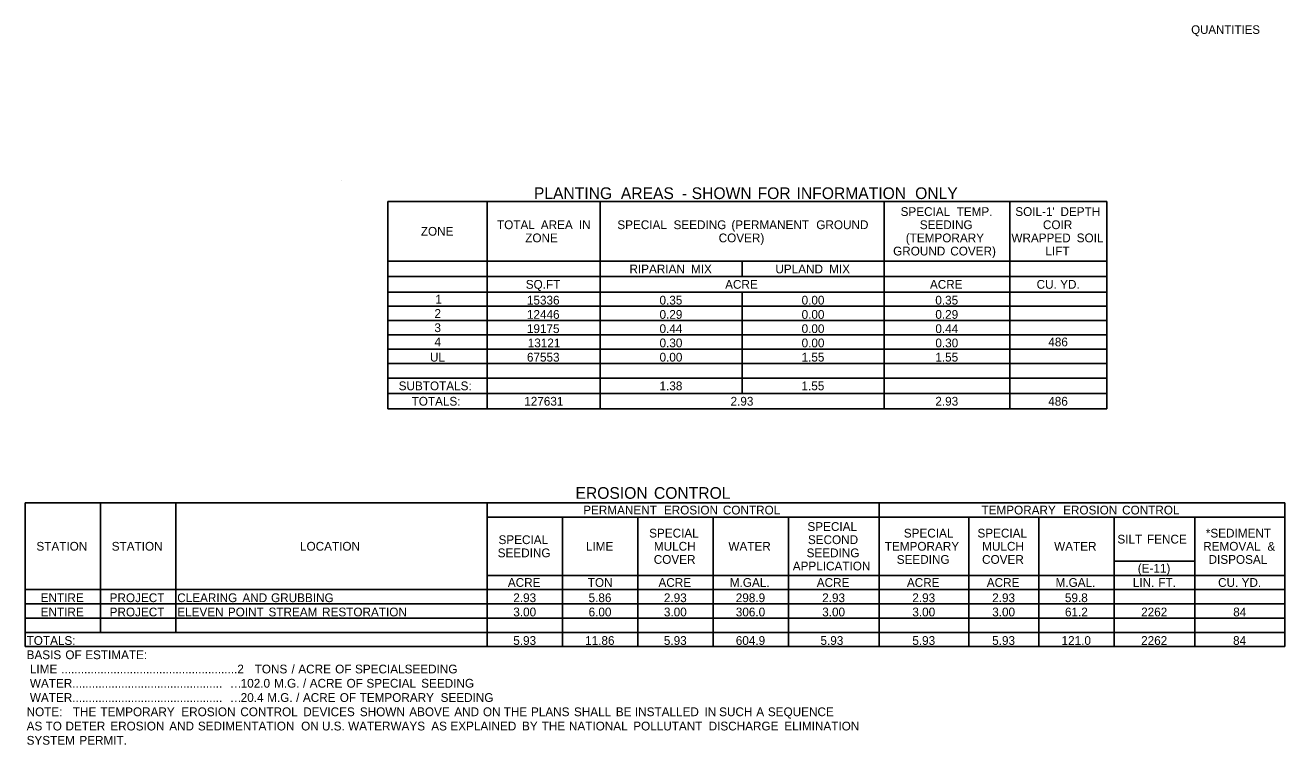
# Model space of a CAD drawing. Extents: x -2001791 to 62654501, y -2521700 to -592476.
# Drawn here: x -2001253 to -2000392, y -592968 to -592476 of the extents above; entities that cross this region are included whole.
import ezdxf

# ---------------------------------------------------------------- set-up
doc = ezdxf.new("R2010")
doc.units = 0
for name, color, linetype in [('Default', 7, 'Continuous'), ('R_Border', 7, 'Continuous'), ('R_Border Prem', 7, 'Continuous')]:
    doc.layers.add(name, color=color, linetype=linetype)

msp = doc.modelspace()

# ---------------------------------------------------------------- linework, layer by layer
at = {"layer": 'Default'}
for p, q in [((-2001005.43, -592596.06), (-2000514.03, -592596.06)), ((-2001005.43, -592738.02), (-2001005.43, -592596.06)), ((-2001005.43, -592738.02), (-2001005.43, -592596.06)), ((-2000937.57, -592738.02), (-2000937.57, -592596.06)), ((-2000860.35, -592738.02), (-2000860.35, -592596.06)), ((-2000666.13, -592738.02), (-2000666.13, -592596.06)), ((-2000580.33, -592738.02), (-2000580.33, -592596.06)), ((-2000514.03, -592738.02), (-2000514.03, -592596.06)), ((-2001005.43, -592637.01), (-2000514.03, -592637.01)), ((-2000763.24, -592647.54), (-2000763.24, -592637.01)), ((-2001005.43, -592647.54), (-2000514.03, -592647.54)), ((-2000580.33, -592647.54), (-2000514.03, -592647.54)), ((-2001005.43, -592658.07), (-2000514.03, -592658.07)), ((-2000763.24, -592727.49), (-2000763.24, -592658.07)), ((-2001005.43, -592667.82), (-2000514.03, -592667.82)), ((-2001005.43, -592677.57), (-2000514.03, -592677.57)), ((-2001005.43, -592687.32), (-2000514.03, -592687.32)), ((-2001005.43, -592697.07), (-2000514.03, -592697.07)), ((-2001005.43, -592706.82), (-2000514.03, -592706.82)), ((-2000580.33, -592706.82), (-2000514.03, -592706.82)), ((-2001005.43, -592716.96), (-2000937.57, -592716.96)), ((-2001005.43, -592716.96), (-2000937.57, -592716.96)), ((-2000937.57, -592716.96), (-2000514.03, -592716.96)), ((-2000937.57, -592716.96), (-2000514.03, -592716.96)), ((-2001005.43, -592727.49), (-2000514.03, -592727.49)), ((-2000937.57, -592738.02), (-2000937.57, -592727.49)), ((-2000580.33, -592727.49), (-2000514.03, -592727.49)), ((-2001005.43, -592738.02), (-2000514.03, -592738.02)), ((-2001253.42, -592802.3), (-2000392.3, -592802.3)), ((-2001253.42, -592900.58), (-2001253.42, -592802.3)), ((-2001253.42, -592900.58), (-2001253.42, -592802.3)), ((-2001201.94, -592890.83), (-2001201.94, -592802.3)), ((-2001150.46, -592890.83), (-2001150.46, -592802.3)), ((-2000937.52, -592900.58), (-2000937.52, -592802.3)), ((-2000669.59, -592812.05), (-2000669.59, -592802.3)), ((-2000669.59, -592900.58), (-2000669.59, -592802.3)), ((-2000392.3, -592900.58), (-2000392.3, -592802.3)), ((-2000937.52, -592812.05), (-2000392.3, -592812.05)), ((-2000886.04, -592900.58), (-2000886.04, -592812.05)), ((-2000834.56, -592900.58), (-2000834.56, -592812.05)), ((-2000783.08, -592900.58), (-2000783.08, -592812.05)), ((-2000731.6, -592900.58), (-2000731.6, -592812.05)), ((-2000608.36, -592900.58), (-2000608.36, -592812.05)), ((-2000560.39, -592900.58), (-2000560.39, -592812.05)), ((-2000508.91, -592900.58), (-2000508.91, -592812.05)), ((-2000453.92, -592900.58), (-2000453.92, -592812.05)), ((-2000508.91, -592842.08), (-2000453.92, -592842.08)), ((-2000937.52, -592851.83), (-2000392.3, -592851.83)), ((-2000886.04, -592881.08), (-2000886.04, -592851.83)), ((-2000834.56, -592881.08), (-2000834.56, -592851.83)), ((-2000783.08, -592881.08), (-2000783.08, -592851.83)), ((-2000731.6, -592881.08), (-2000731.6, -592851.83)), ((-2000669.59, -592881.08), (-2000669.59, -592851.83)), ((-2000608.36, -592881.08), (-2000608.36, -592851.83)), ((-2000560.39, -592881.08), (-2000560.39, -592851.83)), ((-2000508.91, -592881.08), (-2000508.91, -592851.83)), ((-2000453.92, -592851.83), (-2000392.3, -592851.83)), ((-2000453.92, -592881.08), (-2000453.92, -592851.83)), ((-2001253.42, -592861.58), (-2000392.3, -592861.58)), ((-2001201.94, -592881.08), (-2001201.94, -592861.58)), ((-2001150.46, -592881.08), (-2001150.46, -592861.58)), ((-2000937.52, -592881.08), (-2000937.52, -592861.58)), ((-2001253.42, -592871.33), (-2000392.3, -592871.33)), ((-2001253.42, -592881.08), (-2000392.3, -592881.08)), ((-2001253.42, -592890.83), (-2000392.3, -592890.83)), ((-2000937.52, -592900.58), (-2000937.52, -592890.83)), ((-2000886.04, -592900.58), (-2000886.04, -592890.83)), ((-2000608.36, -592900.58), (-2000608.36, -592890.83)), ((-2000560.39, -592900.58), (-2000560.39, -592890.83)), ((-2000453.92, -592900.58), (-2000453.92, -592890.83)), ((-2001253.42, -592900.58), (-2000392.3, -592900.58))]:
    msp.add_line(p, q, dxfattribs=at)
at = {"layer": 'R_Border'}
msp.add_line((-2001037.41, -592582.02), (-2001037.41, -592582.02), dxfattribs=at)

# ---------------------------------------------------------------- texts
at = {"layer": 'Default'}
for s, height, p in [('PLANTING', 8, (-2000905.65, -592594.46)), (' AREAS', 8, (-2000849.19, -592594.46)), (' SHOWN', 8, (-2000800.76, -592594.46)), (' FOR', 8, (-2000755.7, -592594.46)), (' INFORMATION', 8, (-2000729.06, -592594.46)), (' ONLY', 8, (-2000647.99, -592594.46)), (' -', 8, (-2000807.5, -592594.46)), ('SPECIAL', 6, (-2000654.96, -592606.04)), (' TEMP.', 6, (-2000618.87, -592606.04)), ("SOIL-1'", 6, (-2000576.55, -592606.04)), (' DEPTH', 6, (-2000547.91, -592606.04)), ('ZONE', 6, (-2000982.94, -592619.54)), ('TOTAL', 6, (-2000930.85, -592615.04)), (' AREA', 6, (-2000903.16, -592615.04)), (' IN', 6, (-2000877.11, -592615.04)), (' SPECIAL', 6, (-2000850.84, -592615.04)), (' SEEDING', 6, (-2000812.42, -592615.04)), (' (PERMANENT', 6, (-2000772.86, -592615.04)), (' GROUND', 6, (-2000714.82, -592615.04)), ('SEEDING', 6, (-2000641.85, -592615.04)), ('COIR', 6, (-2000557.64, -592615.04)), ('ZONE', 6, (-2000911.56, -592624.04)), ('COVER)', 6, (-2000779.33, -592624.04)), ('(TEMPORARY', 6, (-2000651.42, -592624.04)), ('WRAPPED', 6, (-2000579.22, -592624.04)), (' SOIL', 6, (-2000536.78, -592624.04)), ('GROUND', 6, (-2000660.07, -592633.04)), (' COVER)', 6, (-2000623.22, -592633.04)), ('LIFT', 6, (-2000555.94, -592633.04)), ('RIPARIAN', 6, (-2000840.33, -592645.28)), (' MIX', 6, (-2000800.48, -592645.28)), ('UPLAND', 6, (-2000740.56, -592645.28)), (' MIX', 6, (-2000706.04, -592645.28)), ('SQ.FT', 6, (-2000911.22, -592655.81)), ('ACRE', 6, (-2000774.91, -592655.81)), ('ACRE', 6, (-2000634.9, -592655.81)), ('CU.', 6, (-2000561.97, -592655.81)), (' YD.', 6, (-2000548.11, -592655.81)), ('1', 6, (-2000973.06, -592665.95)), ('15336', 6, (-2000910.42, -592666.62)), ('0.35', 6, (-2000819.78, -592666.62)), ('0.00', 6, (-2000722.64, -592666.62)), ('0.35', 6, (-2000631.22, -592666.62)), ('2', 6, (-2000973.61, -592675.7)), ('12446', 6, (-2000910.42, -592676.37)), ('0.29', 6, (-2000819.76, -592676.37)), ('0.00', 6, (-2000722.64, -592676.37)), ('0.29', 6, (-2000631.2, -592676.37)), ('3', 6, (-2000973.64, -592685.45)), ('19175', 6, (-2000910.44, -592686.12)), ('0.44', 6, (-2000819.75, -592686.12)), ('0.00', 6, (-2000722.64, -592686.12)), ('0.44', 6, (-2000631.18, -592686.12)), ('4', 6, (-2000973.63, -592695.2)), ('13121', 6, (-2000909.84, -592695.87)), ('0.30', 6, (-2000819.75, -592695.87)), ('0.00', 6, (-2000722.64, -592695.87)), ('0.30', 6, (-2000631.18, -592695.87)), ('486', 6, (-2000553.98, -592695.2)), ('UL', 6, (-2000976.71, -592705.62)), ('67553', 6, (-2000910.42, -592705.62)), ('0.00', 6, (-2000819.75, -592705.62)), ('1.55', 6, (-2000722.67, -592705.62)), ('1.55', 6, (-2000631.22, -592705.62)), ('SUBTOTALS:', 6, (-2000998.1, -592725.23)), ('1.38', 6, (-2000819.76, -592725.23)), ('1.55', 6, (-2000722.71, -592725.23)), ('TOTALS:', 6, (-2000989.25, -592735.76)), ('127631', 6, (-2000912.26, -592735.76)), ('2.93', 6, (-2000771.21, -592735.76)), ('2.93', 6, (-2000631.2, -592735.76)), ('486', 6, (-2000554.02, -592735.76)), ('EROSION', 8, (-2000877.21, -592799.47)), (' CONTROL', 8, (-2000826.55, -592799.47)), ('PERMANENT', 6, (-2000871.94, -592810.17)), (' EROSION', 6, (-2000819.01, -592810.17)), (' CONTROL', 6, (-2000778.69, -592810.17)), ('TEMPORARY', 6, (-2000599.66, -592810.17)), (' EROSION', 6, (-2000546.08, -592810.17)), (' CONTROL', 6, (-2000505.76, -592810.17)), ('SPECIAL', 6, (-2000826.86, -592825.94)), ('SPECIAL', 6, (-2000718.64, -592821.44)), ('    SPECIAL', 6, (-2000661.67, -592825.94)), ('SPECIAL', 6, (-2000602.42, -592825.94)), ('*SEDIMENT', 6, (-2000446.31, -592825.94)), ('STATION', 6, (-2001245.74, -592834.94)), ('STATION', 6, (-2001194.26, -592834.94)), ('LOCATION', 6, (-2001065.54, -592834.94)), ('SPECIAL', 6, (-2000929.82, -592830.44)), ('LIME', 6, (-2000870.1, -592834.94)), ('MULCH', 6, (-2000823.63, -592834.94)), ('WATER', 6, (-2000772.69, -592834.94)), ('SECOND', 6, (-2000718.32, -592830.44)), ('TEMPORARY', 6, (-2000665.77, -592834.94)), ('MULCH', 6, (-2000599.19, -592834.94)), ('WATER', 6, (-2000550, -592834.94)), ('SILT', 6, (-2000506.74, -592830.06)), (' FENCE', 6, (-2000488.75, -592830.06)), ('REMOVAL', 6, (-2000448.07, -592834.94)), (' &', 6, (-2000406.4, -592834.94)), ('SEEDING', 6, (-2000930.39, -592839.44)), ('COVER', 6, (-2000823.71, -592843.94)), ('SEEDING', 6, (-2000719.21, -592839.44)), ('SEEDING', 6, (-2000657.59, -592843.94)), ('COVER', 6, (-2000599.26, -592843.94)), ('DISPOSAL', 6, (-2000444.41, -592843.94)), ('APPLICATION', 6, (-2000728.67, -592848.44)), ('(E-11)', 6, (-2000492.84, -592849.95)), ('ACRE', 6, (-2000923.45, -592859.7)), ('TON', 6, (-2000868.81, -592859.7)), ('ACRE', 6, (-2000820.49, -592859.7)), ('M.GAL.', 6, (-2000771.72, -592859.7)), ('ACRE', 6, (-2000712.26, -592859.7)), ('ACRE', 6, (-2000650.64, -592859.7)), ('ACRE', 6, (-2000596.04, -592859.7)), ('M.GAL.', 6, (-2000549.03, -592859.7)), ('LIN.', 6, (-2000496.2, -592859.7)), (' FT.', 6, (-2000480.95, -592859.7)), ('CU.', 6, (-2000437.9, -592859.7)), (' YD.', 6, (-2000424.04, -592859.7)), ('ENTIRE', 6, (-2001242.83, -592870.13)), ('PROJECT', 6, (-2001195.68, -592870.13)), ('CLEARING', 6, (-2001149.48, -592870.13)), (' AND', 6, (-2001107.15, -592870.13)), (' GRUBBING', 6, (-2001087.57, -592870.13)), ('2.93', 6, (-2000919.74, -592870.13)), ('5.86', 6, (-2000868.26, -592870.13)), ('2.93', 6, (-2000816.78, -592870.13)), ('298.9', 6, (-2000767.64, -592870.13)), ('2.93', 6, (-2000708.56, -592870.13)), ('2.93', 6, (-2000646.94, -592870.13)), ('2.93', 6, (-2000592.34, -592870.13)), ('59.8', 6, (-2000542.62, -592870.13)), ('ENTIRE', 6, (-2001242.83, -592879.88)), ('PROJECT', 6, (-2001195.68, -592879.88)), ('ELEVEN', 6, (-2001149.48, -592879.88)), (' POINT', 6, (-2001117.08, -592879.88)), (' STREAM', 6, (-2001089.31, -592879.88)), (' RESTORATION', 6, (-2001052.67, -592879.88)), ('3.00', 6, (-2000919.73, -592879.88)), ('6.00', 6, (-2000868.25, -592879.88)), ('3.00', 6, (-2000816.77, -592879.88)), ('306.0', 6, (-2000767.62, -592879.88)), ('3.00', 6, (-2000708.55, -592879.88)), ('3.00', 6, (-2000646.93, -592879.88)), ('3.00', 6, (-2000592.33, -592879.88)), ('61.2', 6, (-2000542.58, -592879.88)), ('2262', 6, (-2000490.51, -592879.88)), ('84', 6, (-2000427.57, -592879.88)), ('TOTALS:', 6, (-2001252.44, -592899.38)), ('5.93', 6, (-2000919.75, -592899.38)), ('11.86', 6, (-2000870.63, -592899.38)), ('5.93', 6, (-2000816.79, -592899.38)), ('604.9', 6, (-2000767.63, -592899.38)), ('5.93', 6, (-2000709.73, -592899.38)), ('5.93', 6, (-2000646.95, -592899.38)), ('5.93', 6, (-2000592.35, -592899.38)), ('121.0', 6, (-2000544.93, -592899.38)), ('2262', 6, (-2000490.52, -592899.38)), ('84', 6, (-2000427.67, -592899.38)), ('BASIS', 6, (-2001252.44, -592909.13)), (' OF', 6, (-2001228.18, -592909.13)), (' ESTIMATE:', 6, (-2001214.6, -592909.13)), (' LIME', 6, (-2001252.44, -592918.88)), (' ......................................................2', 6, (-2001231, -592918.88)), (' TONS', 6, (-2001098.76, -592918.88)), (' /', 6, (-2001073.58, -592918.88)), (' ACRE', 6, (-2001068.92, -592918.88)), (' OF', 6, (-2001043.74, -592918.88)), (' SPECIALSEEDING', 6, (-2001030.16, -592918.88)), (' WATER..............................................', 6, (-2001252.44, -592928.63)), ('102.0', 6, (-2001106.1, -592928.63)), (' M.G.', 6, (-2001085.53, -592928.63)), (' /', 6, (-2001065.78, -592928.63)), (' ACRE', 6, (-2001061.12, -592928.63)), (' OF', 6, (-2001035.94, -592928.63)), (' SPECIAL', 6, (-2001022.35, -592928.63)), (' SEEDING', 6, (-2000984.91, -592928.63)), (' WATER..............................................', 6, (-2001252.44, -592938.38)), ('…', 6, (-2001113.5, -592928.63)), ('20.4', 6, (-2001106.1, -592938.38)), (' M.G.', 6, (-2001090.2, -592938.38)), (' /', 6, (-2001070.44, -592938.38)), (' ACRE', 6, (-2001065.78, -592938.38)), (' OF', 6, (-2001040.61, -592938.38)), (' TEMPORARY', 6, (-2001027.02, -592938.38)), (' SEEDING', 6, (-2000971.65, -592938.38)), ('…', 6, (-2001113.5, -592938.38)), ('NOTE:', 6, (-2001252.44, -592948.13)), ('   THE', 6, (-2001227.56, -592948.13)), (' TEMPORARY', 6, (-2001204.25, -592948.13)), (' EROSION', 6, (-2001148.88, -592948.13)), (' CONTROL', 6, (-2001108.57, -592948.13)), (' DEVICES', 6, (-2001065.55, -592948.13)), (' SHOWN', 6, (-2001026.85, -592948.13)), (' ABOVE', 6, (-2000993.08, -592948.13)), (' AND', 6, (-2000962.3, -592948.13)), (' ON', 6, (-2000942.72, -592948.13)), (' THE', 6, (-2000928.5, -592948.13)), (' PLANS', 6, (-2000909.85, -592948.13)), (' SHALL', 6, (-2000880.47, -592948.13)), (' BE', 6, (-2000851.88, -592948.13)), (' INSTALLED', 6, (-2000838.81, -592948.13)), (' IN', 6, (-2000791.28, -592948.13)), (' SUCH', 6, (-2000781.25, -592948.13)), (' A', 6, (-2000755.84, -592948.13)), (' SEQUENCE', 6, (-2000747.91, -592948.13)), ('AS', 6, (-2001252.44, -592957.88)), (' TO', 6, (-2001241.7, -592957.88)), (' DETER', 6, (-2001228.1, -592957.88)), (' EROSION', 6, (-2001197.47, -592957.88)), (' AND', 6, (-2001157.16, -592957.88)), (' SEDIMENTATION', 6, (-2001137.58, -592957.88)), (' ON', 6, (-2001067, -592957.88)), (' U.S.', 6, (-2001052.78, -592957.88)), (' WATERWAYS', 6, (-2001034.88, -592957.88)), (' AS', 6, (-2000978.03, -592957.88)), (' EXPLAINED', 6, (-2000964.95, -592957.88)), (' BY', 6, (-2000916.01, -592957.88)), (' THE', 6, (-2000902.56, -592957.88)), (' NATIONAL', 6, (-2000883.91, -592957.88)), (' POLLUTANT', 6, (-2000839.95, -592957.88)), (' DISCHARGE', 6, (-2000788.41, -592957.88)), (' ELIMINATION', 6, (-2000736.69, -592957.88)), ('SYSTEM', 6, (-2001252.44, -592967.63)), (' PERMIT.', 6, (-2001218.6, -592967.63))]:
    msp.add_text(s, height=height, dxfattribs=at).set_placement(p)
at = {"layer": 'R_Border Prem'}
msp.add_text('QUANTITIES', height=5.862, dxfattribs=at).set_placement((-2000456.3, -592481.51))

doc.saveas('drawing.dxf')
